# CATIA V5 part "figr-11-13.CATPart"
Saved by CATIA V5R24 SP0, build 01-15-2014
Part number: Part1
Bounding box of the stored display mesh (mm): x -10 to 5, y -10.258 to 7.91, z -1.915 to 2.054
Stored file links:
  D:\KAVITA\CATIA V5-6R2014 Project_ Kavita\CATIA V5-6R2014_partfiles\Partfiles\c11_catia_v5-6r2014_prt\figr-11-13.CATPart
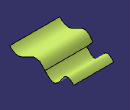
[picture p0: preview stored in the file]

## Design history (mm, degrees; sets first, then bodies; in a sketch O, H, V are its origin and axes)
Set1
  Sketch1 on yz-plane, origin (0, 0, 0), H (0, 1, 0), V (0, 0, 1)
    spline S1 through (-0.358, 0) (-3.1664, 2.0538) (-6.7822, 0.4079) (-10.2576, 1.6423)
    point P1 (-0.358, 0)
    coincidence: P1 H
  Extrude1: Element1 Sketch1, Lim1 5, Lim2 10, Direction yz-plane
  Sketch2 on yz-plane, origin (0, 0, 0), H (0, 1, 0), V (0, 0, 1)
    spline S1 through (0, 0) (3.5471, -1.4404) (5.7957, 1.2855) (7.9098, 0)
    point P1 (0, 0)
    point P2 (7.9098, 0)
    coincidence: P1 O, P2 H
  Extrude2: Element1 Sketch2, Lim1 4, Lim2 8, Direction yz-plane
  Healing1: BodyToHeal (Extrude2; Extrude1), TangencyAngle 0.5, SharpnessAngle 0.5
Body1 (main body)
